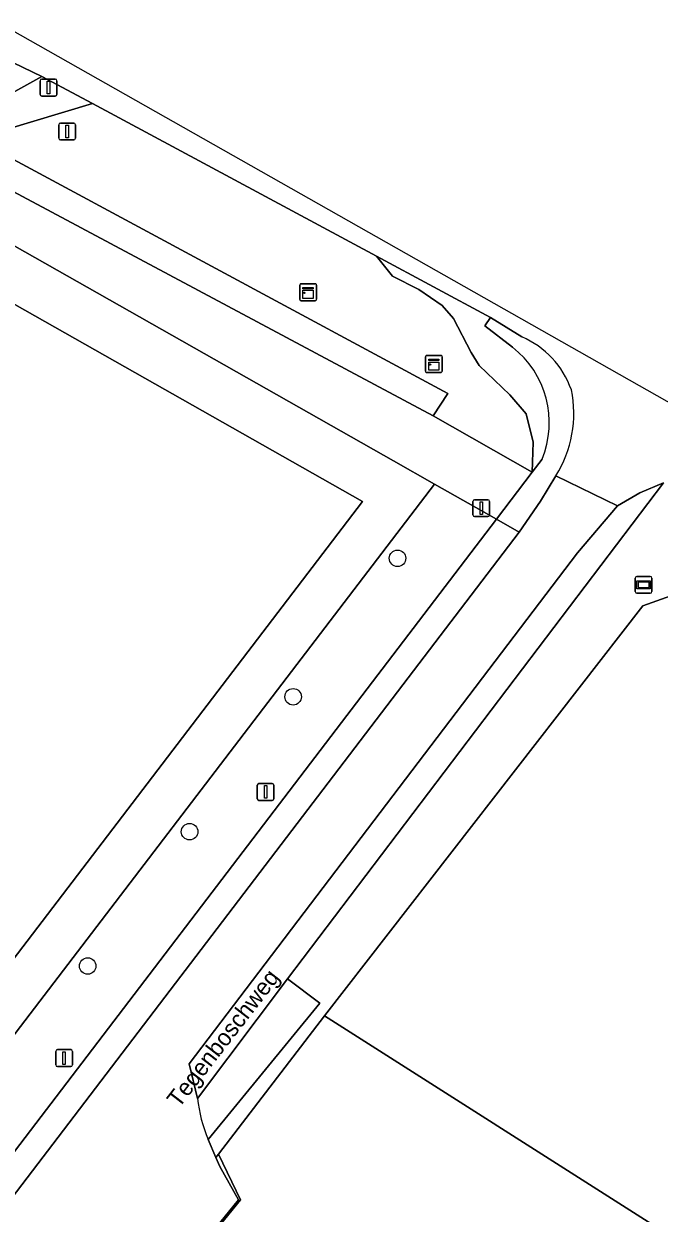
# Model space of a CAD drawing. Extents: x 156502 to 159075, y 384229 to 386100.
# Drawn here: x 157160.6 to 157198.2, y 386014.1 to 386084.5 of the extents above; entities that cross this region are included whole.
import ezdxf

# ---------------------------------------------------------------- set-up
doc = ezdxf.new("R2010")
doc.units = 0
for name, color, linetype in [('IMGEO_Berm_groen', 7, 'Continuous'), ('IMGEO_Berm_halfverhard', 7, 'Continuous'), ('IMGEO_Boom', 7, 'Continuous'), ('IMGEO_Erf', 7, 'Continuous'), ('IMGEO_Fietspad_gesloten', 7, 'Continuous'), ('IMGEO_Gemengd_bos', 7, 'Continuous'), ('IMGEO_Greppel_droge_sloot', 7, 'Continuous'), ('IMGEO_Groenvoorziening', 7, 'Continuous'), ('IMGEO_Haag', 7, 'Continuous'), ('IMGEO_Hek', 7, 'Continuous'), ('IMGEO_Kast', 7, 'Continuous'), ('IMGEO_Lichtmast', 7, 'Continuous'), ('IMGEO_Openbare_ruimte_label', 7, 'Continuous'), ('IMGEO_Rijbaan_lokaal_gesloten', 7, 'Continuous'), ('IMGEO_Rijbaan_lokaal_halfverhard', 7, 'Continuous'), ('IMGEO_Verkeersbordpaal', 7, 'Continuous'), ('IMGEO_Verklikker', 7, 'Continuous')]:
    doc.layers.add(name, color=color, linetype=linetype)

msp = doc.modelspace()

# ---------------------------------------------------------------- linework, layer by layer
at = {"layer": 'IMGEO_Berm_groen'}
msp.add_lwpolyline([(157164.639, 386079.76), (157157.67, 386077.678), (157185.693, 386062.601), (157184.83, 386061.273), (157190.693, 386057.95), (157190.736, 386059.722), (157190.328, 386061.393), (157189.36, 386062.527), (157187.537, 386064.254), (157187.068, 386065.019), (157186.032, 386067.042), (157185.351, 386067.805), (157183.979, 386068.757), (157182.415, 386069.546), (157181.467, 386070.721)], close=True, dxfattribs=at)
for points in [[(157188.566, 386055.162), (157184.907, 386057.234), (157021.918, 385843.894)], [(157027.777, 385843.918), (157039.623, 385859.739), (157076.319, 385908.026), (157188.566, 386055.162)]]:
    msp.add_lwpolyline(points, dxfattribs=at)
at = {"layer": 'IMGEO_Berm_halfverhard'}
msp.add_lwpolyline([(157028.972, 385842.844), (157041.694, 385859.803), (157077.656, 385907.175), (157189.916, 386054.397), (157188.566, 386055.162), (157076.319, 385908.026), (157039.623, 385859.739), (157027.777, 385843.918), (157027.693, 385843.804)], dxfattribs=at)
at = {"layer": 'IMGEO_Boom'}
for centre in [(157182.711, 386052.847), (157176.529, 386044.651), (157170.396, 386036.664), (157164.36, 386028.715)]:
    msp.add_circle(centre, 0.489, dxfattribs=at)
at = {"layer": 'IMGEO_Erf'}
msp.add_lwpolyline([(157291.797, 385905.791), (157257.608, 385922.624), (157240.005, 385933.444), (157265.451, 385970.38), (157218.887, 386000), (157178.386, 386025.763), (157172.105, 386017.583), (157173.41, 386014.873), (157171.433, 386012.444), (157168.449, 386012.84), (157142.059, 385978.178), (157143.255, 385977.636), (157149.373, 385974.096), (157147.133, 385970.598), (157142.453, 385973.429), (157107.2, 385927.397), (157118.024, 385920.915), (157113.026, 385912.196)], dxfattribs=at)
at = {"layer": 'IMGEO_Fietspad_gesloten'}
msp.add_lwpolyline([(157073.59, 386031.17), (157090.661, 386041.292), (157160.05, 386080.464), (157161.641, 386081.37), (157157.693, 386083.251), (157155.519, 386082.013), (157088.994, 386044.123), (157072.063, 386034.271)], dxfattribs=at)
at = {"layer": 'IMGEO_Gemengd_bos'}
msp.add_lwpolyline([(157202.772, 386052.013), (157197.243, 386050.03), (157178.386, 386025.763), (157218.887, 386000), (157265.451, 385970.38), (157240.005, 385933.444), (157257.608, 385922.624), (157291.797, 385905.791), (157297.291, 385911.485), (157341.884, 385885.733), (157336.953, 385876.45), (157374.534, 385855.112), (157371.55, 385848.547), (157374.235, 385846.993), (157374.53, 385846.953), (157374.766, 385847.134), (157419.092, 385923.885)], dxfattribs=at)
at = {"layer": 'IMGEO_Greppel_droge_sloot'}
msp.add_lwpolyline([(157157.67, 386077.678), (157157.203, 386076.568), (157157.01, 386076.109), (157184.83, 386061.273), (157185.693, 386062.601)], close=True, dxfattribs=at)
at = {"layer": 'IMGEO_Groenvoorziening'}
for points in [[(157061.311, 386021.393), (157085.574, 386036.103), (157115.223, 386052.978), (157120.284, 386055.801), (157152.797, 386073.936), (157157.01, 386076.109), (157157.203, 386076.568), (157157.67, 386077.678), (157164.639, 386079.76), (157161.641, 386081.37), (157160.05, 386080.464), (157090.661, 386041.292), (157073.59, 386031.17)], [(157021.918, 385843.894), (157184.907, 386057.234), (157182.471, 386058.613), (157155.614, 386073.823), (157152.797, 386073.936)], [(156974.125, 385919.066), (156965.937, 385930.622), (156962.206, 385939.803), (156996.417, 385971.473), (157033.353, 385999.519), (157071.795, 386022.274), (157107.644, 386042.332), (157141.859, 386060.718), (157157.667, 386069.213), (157180.634, 386056.206), (157071.087, 385912.699)], [(157198.463, 386057.309), (157176.201, 386027.966), (157178.116, 386026.513), (157171.498, 386018.457), (157171.955, 386017.388), (157172.105, 386017.583), (157178.386, 386025.763), (157197.243, 386050.03), (157202.772, 386052.013)], [(157171.498, 386018.457), (157178.116, 386026.513), (157176.201, 386027.966), (157170.869, 386020.883)]]:
    msp.add_lwpolyline(points, dxfattribs=at)
for points in [[(157190.693, 386057.95), (157184.83, 386061.273), (157157.01, 386076.109), (157152.797, 386073.936), (157155.614, 386073.823), (157182.471, 386058.613), (157184.907, 386057.234), (157188.566, 386055.162)], [(157180.634, 386056.206), (157157.667, 386069.213), (157141.859, 386060.718), (157119.898, 386031.613), (157112.225, 386027.38), (157100.054, 386012.563), (157083.49, 386002.815), (157074.431, 385999.041), (157069.734, 385990.233), (157066.45, 385980.334), (157048.46, 385958.059), (157049.783, 385948.534), (157024.383, 385917.578), (157012.477, 385911.492), (157001.337, 385911.378), (156999.468, 385912.632), (156989.301, 385898.643), (156990.12, 385896.678), (157010.156, 385862.563), (157019.003, 385846.692), (157019.844, 385845.786), (157029.054, 385857.935), (157071.087, 385912.699)], [(157168.449, 386012.84), (157171.433, 386012.444), (157173.41, 386014.873), (157172.105, 386017.583), (157171.955, 386017.388), (157172.189, 386016.84), (157173.283, 386014.882), (157171.41, 386012.563), (157170.093, 386012.849), (157168.575, 386013.006)]]:
    msp.add_lwpolyline(points, close=True, dxfattribs=at)
msp.add_arc((157178.911, 386021.674), 8.081, 185.61452, 203.45603, dxfattribs=at)
at = {"layer": 'IMGEO_Haag'}
msp.add_lwpolyline([(157171.498, 386018.457), (157178.116, 386026.513), (157176.201, 386027.966), (157170.869, 386020.883)], dxfattribs=at)
msp.add_arc((157178.911, 386021.674), 8.081, 185.61452, 203.45603, dxfattribs=at)
at = {"layer": 'IMGEO_Hek'}
for points in [[(157182.471, 386058.613), (157155.614, 386073.823), (157152.797, 386073.936)], [(157184.907, 386057.234), (157182.471, 386058.613)], [(157188.566, 386055.162), (157184.907, 386057.234)], [(157189.916, 386054.397), (157188.566, 386055.162)], [(157173.41, 386014.873), (157172.105, 386017.583), (157178.386, 386025.763)], [(157178.386, 386025.763), (157218.887, 386000), (157265.451, 385970.38), (157240.005, 385933.444)], [(157171.433, 386012.444), (157173.41, 386014.873)]]:
    msp.add_lwpolyline(points, dxfattribs=at)
at = {"layer": 'IMGEO_Kast'}
for p, q in [((157176.916, 386068.166), (157176.916, 386069.007)), ((157176.916, 386069.007), (157176.916, 386068.166)), ((157176.991, 386069.091), (157177.832, 386069.091)), ((157177.832, 386069.091), (157176.991, 386069.091)), ((157177.916, 386069.016), (157177.916, 386068.175)), ((157177.916, 386068.175), (157177.916, 386069.016)), ((157177.841, 386068.091), (157177, 386068.091)), ((157177, 386068.091), (157177.841, 386068.091)), ((157184.361, 386063.922), (157184.361, 386064.763)), ((157184.361, 386064.763), (157184.361, 386063.922)), ((157184.436, 386064.847), (157185.277, 386064.847)), ((157185.277, 386064.847), (157184.436, 386064.847)), ((157185.361, 386064.772), (157185.361, 386063.931)), ((157185.361, 386063.931), (157185.361, 386064.772)), ((157185.286, 386063.847), (157184.445, 386063.847)), ((157184.445, 386063.847), (157185.286, 386063.847))]:
    msp.add_line(p, q, dxfattribs=at)
for points in [[(157177.111, 386068.881), (157177.711, 386068.881), (157177.711, 386068.796), (157177.111, 386068.796), (157177.111, 386068.881)], [(157177.111, 386068.706), (157177.711, 386068.706), (157177.711, 386068.217), (157177.111, 386068.217), (157177.111, 386068.706)], [(157184.556, 386064.637), (157185.156, 386064.637), (157185.156, 386064.552), (157184.556, 386064.552), (157184.556, 386064.637)], [(157184.556, 386064.462), (157185.156, 386064.462), (157185.156, 386063.973), (157184.556, 386063.973), (157184.556, 386064.462)]]:
    msp.add_lwpolyline(points, dxfattribs=at)
for centre in [(157177.195, 386068.555), (157184.64, 386064.311)]:
    msp.add_circle(centre, 0.0377, dxfattribs=at)
for centre, start, end in [((157176.994, 386069.013), 92.4484, 184.28452), ((157176.994, 386069.013), 92.4484, 184.28452), ((157177.838, 386069.013), 2.4484, 94.28452), ((157177.838, 386069.013), 2.4484, 94.28452), ((157177.838, 386068.169), 272.4484, 4.28452), ((157177.838, 386068.169), 272.4484, 4.28452), ((157176.994, 386068.169), 182.4484, 274.28452), ((157176.994, 386068.169), 182.4484, 274.28452), ((157184.439, 386064.769), 92.4484, 184.28452), ((157184.439, 386064.769), 92.4484, 184.28452), ((157185.283, 386064.769), 2.4484, 94.28452), ((157185.283, 386064.769), 2.4484, 94.28452), ((157184.439, 386063.925), 182.4484, 274.28452), ((157184.439, 386063.925), 182.4484, 274.28452), ((157185.283, 386063.925), 272.4484, 4.28452), ((157185.283, 386063.925), 272.4484, 4.28452)]:
    msp.add_arc(centre, 0.0779, start, end, dxfattribs=at)
at = {"layer": 'IMGEO_Lichtmast'}
for p, q in [((157187.177, 386055.412), (157187.177, 386056.212)), ((157187.177, 386056.212), (157187.177, 386055.412)), ((157187.277, 386056.312), (157188.067, 386056.312)), ((157188.067, 386056.312), (157187.277, 386056.312)), ((157188.167, 386056.212), (157188.167, 386055.412)), ((157188.167, 386055.412), (157188.167, 386056.212)), ((157188.067, 386055.312), (157187.277, 386055.312)), ((157187.277, 386055.312), (157188.067, 386055.312)), ((157174.405, 386038.617), (157174.405, 386039.417)), ((157174.405, 386039.417), (157174.405, 386038.617)), ((157174.505, 386039.517), (157175.295, 386039.517)), ((157175.295, 386039.517), (157174.505, 386039.517)), ((157175.395, 386039.417), (157175.395, 386038.617)), ((157175.395, 386038.617), (157175.395, 386039.417)), ((157175.295, 386038.517), (157174.505, 386038.517)), ((157174.505, 386038.517), (157175.295, 386038.517)), ((157162.465, 386022.865), (157162.465, 386023.665)), ((157162.465, 386023.665), (157162.465, 386022.865)), ((157162.565, 386023.765), (157163.355, 386023.765)), ((157163.355, 386023.765), (157162.565, 386023.765)), ((157163.455, 386023.665), (157163.455, 386022.865)), ((157163.455, 386022.865), (157163.455, 386023.665)), ((157163.355, 386022.765), (157162.565, 386022.765)), ((157162.565, 386022.765), (157163.355, 386022.765))]:
    msp.add_line(p, q, dxfattribs=at)
for points in [[(157187.597, 386056.187), (157187.747, 386056.187), (157187.747, 386055.437), (157187.597, 386055.437), (157187.597, 386056.187)], [(157174.825, 386039.392), (157174.975, 386039.392), (157174.975, 386038.642), (157174.825, 386038.642), (157174.825, 386039.392)], [(157162.885, 386023.64), (157163.035, 386023.64), (157163.035, 386022.89), (157162.885, 386022.89), (157162.885, 386023.64)]]:
    msp.add_lwpolyline(points, dxfattribs=at)
for centre, start, end in [((157187.277, 386056.212), 90, 180), ((157187.277, 386056.212), 90, 180), ((157188.067, 386056.212), 0, 90), ((157188.067, 386056.212), 360, 90), ((157187.277, 386055.412), 180, 270), ((157187.277, 386055.412), 180, 270), ((157188.067, 386055.412), 270, 0), ((157188.067, 386055.412), 270, 0), ((157174.505, 386039.417), 90, 180), ((157174.505, 386039.417), 90, 180), ((157175.295, 386039.417), 0, 90), ((157175.295, 386039.417), 360, 90), ((157174.505, 386038.617), 180, 270), ((157174.505, 386038.617), 180, 270), ((157175.295, 386038.617), 270, 0), ((157175.295, 386038.617), 270, 0), ((157162.565, 386023.665), 90, 180), ((157162.565, 386023.665), 90, 180), ((157163.355, 386023.665), 0, 90), ((157163.355, 386023.665), 360, 90), ((157162.565, 386022.865), 180, 270), ((157162.565, 386022.865), 180, 270), ((157163.355, 386022.865), 270, 0), ((157163.355, 386022.865), 270, 0)]:
    msp.add_arc(centre, 0.1, start, end, dxfattribs=at)
at = {"layer": 'IMGEO_Rijbaan_lokaal_gesloten'}
for points in [[(157207.296, 386057.251), (157159.198, 386084.481), (157157.693, 386083.251), (157161.641, 386081.37), (157164.639, 386079.76), (157181.467, 386070.721), (157188.215, 386067.097), (157190.071, 386065.952)], [(157170.869, 386020.883), (157170.373, 386022.922), (157193.363, 386053.168), (157195.745, 386055.945), (157192.084, 386057.732), (157191.18, 386056.232), (157189.916, 386054.397), (157077.656, 385907.175), (157041.694, 385859.803), (157028.972, 385842.844), (157031.66, 385840.505)], [(157192.084, 386057.732), (157195.745, 386055.945), (157197.059, 386056.715), (157198.463, 386057.309)], [(157090.505, 385918.168), (157162.952, 386013.182), (157164.84, 386013.11), (157168.146, 386013.05), (157168.575, 386013.006), (157170.093, 386012.849), (157171.41, 386012.563), (157173.283, 386014.882), (157172.189, 386016.84), (157171.955, 386017.388), (157171.498, 386018.457)]]:
    msp.add_lwpolyline(points, dxfattribs=at)
for centre, radius, start, end in [((157187.955, 386061.029), 5.359, 19.5405, 66.73871), ((157186.265, 386061.413), 6.886, 327.68416, 11.79929), ((157178.911, 386021.674), 8.081, 185.61452, 203.45603)]:
    msp.add_arc(centre, radius, start, end, dxfattribs=at)
at = {"layer": 'IMGEO_Rijbaan_lokaal_halfverhard'}
for points in [[(157189.519, 386065.342), (157187.873, 386066.607), (157188.215, 386067.097), (157181.467, 386070.721), (157182.415, 386069.546), (157183.979, 386068.757), (157185.351, 386067.805), (157186.032, 386067.042), (157187.068, 386065.019), (157187.537, 386064.254), (157189.36, 386062.527), (157190.328, 386061.393), (157190.736, 386059.722), (157190.693, 386057.95), (157191.268, 386058.707)], [(157190.071, 386065.952), (157188.215, 386067.097), (157187.873, 386066.607), (157189.519, 386065.342)], [(157191.268, 386058.707), (157190.693, 386057.95), (157188.566, 386055.162), (157189.916, 386054.397), (157191.18, 386056.232), (157192.084, 386057.732)]]:
    msp.add_lwpolyline(points, dxfattribs=at)
msp.add_lwpolyline([(157198.463, 386057.309), (157197.059, 386056.715), (157195.745, 386055.945), (157193.363, 386053.168), (157170.373, 386022.922), (157170.869, 386020.883), (157176.201, 386027.966)], close=True, dxfattribs=at)
for centre, radius, start, end in [((157187.955, 386061.029), 5.359, 19.5405, 66.73871), ((157186.023, 386060.872), 5.674, 337.56475, 51.96998), ((157186.023, 386060.872), 5.674, 337.56475, 51.96998), ((157186.265, 386061.413), 6.886, 327.68416, 11.79929)]:
    msp.add_arc(centre, radius, start, end, dxfattribs=at)
at = {"layer": 'IMGEO_Verkeersbordpaal'}
for p, q in [((157161.545, 386080.306), (157161.545, 386081.106)), ((157161.545, 386081.106), (157161.545, 386080.306)), ((157161.645, 386081.206), (157162.435, 386081.206)), ((157162.435, 386081.206), (157161.645, 386081.206)), ((157162.535, 386081.106), (157162.535, 386080.306)), ((157162.535, 386080.306), (157162.535, 386081.106)), ((157162.435, 386080.206), (157161.645, 386080.206)), ((157161.645, 386080.206), (157162.435, 386080.206)), ((157162.647, 386077.704), (157162.647, 386078.504)), ((157162.647, 386078.504), (157162.647, 386077.704)), ((157162.747, 386078.604), (157163.537, 386078.604)), ((157163.537, 386078.604), (157162.747, 386078.604)), ((157163.637, 386078.504), (157163.637, 386077.704)), ((157163.637, 386077.704), (157163.637, 386078.504)), ((157163.537, 386077.604), (157162.747, 386077.604)), ((157162.747, 386077.604), (157163.537, 386077.604))]:
    msp.add_line(p, q, dxfattribs=at)
for points in [[(157161.965, 386081.081), (157162.115, 386081.081), (157162.115, 386080.331), (157161.965, 386080.331), (157161.965, 386081.081)], [(157163.067, 386078.479), (157163.217, 386078.479), (157163.217, 386077.729), (157163.067, 386077.729), (157163.067, 386078.479)]]:
    msp.add_lwpolyline(points, dxfattribs=at)
for centre, start, end in [((157161.645, 386081.106), 90, 180), ((157161.645, 386081.106), 90, 180), ((157162.435, 386081.106), 0, 90), ((157162.435, 386081.106), 360, 90), ((157161.645, 386080.306), 180, 270), ((157161.645, 386080.306), 180, 270), ((157162.435, 386080.306), 270, 0), ((157162.435, 386080.306), 270, 0), ((157162.747, 386078.504), 90, 180), ((157162.747, 386078.504), 90, 180), ((157163.537, 386078.504), 0, 90), ((157163.537, 386078.504), 360, 90), ((157162.747, 386077.704), 180, 270), ((157162.747, 386077.704), 180, 270), ((157163.537, 386077.704), 270, 0), ((157163.537, 386077.704), 270, 0)]:
    msp.add_arc(centre, 0.1, start, end, dxfattribs=at)
at = {"layer": 'IMGEO_Verklikker'}
for p, q in [((157196.788, 386050.876), (157196.788, 386051.676)), ((157196.788, 386051.676), (157196.788, 386050.876)), ((157196.888, 386051.776), (157197.678, 386051.776)), ((157197.678, 386051.776), (157196.888, 386051.776)), ((157197.778, 386051.676), (157197.778, 386050.876)), ((157197.778, 386050.876), (157197.778, 386051.676)), ((157197.678, 386050.776), (157196.888, 386050.776)), ((157196.888, 386050.776), (157197.678, 386050.776))]:
    msp.add_line(p, q, dxfattribs=at)
for points in [[(157196.889, 386051.508), (157197.677, 386051.508), (157197.677, 386051.044), (157196.889, 386051.044), (157196.889, 386051.508)], [(157196.954, 386051.443), (157196.954, 386051.109), (157197.612, 386051.109), (157197.612, 386051.443), (157196.954, 386051.443)]]:
    msp.add_lwpolyline(points, dxfattribs=at)
for centre, start, end in [((157196.888, 386051.676), 90, 180), ((157196.888, 386051.676), 90, 180), ((157197.678, 386051.676), 0, 90), ((157197.678, 386051.676), 360, 90), ((157196.888, 386050.876), 180, 270), ((157196.888, 386050.876), 180, 270), ((157197.678, 386050.876), 270, 0), ((157197.678, 386050.876), 270, 0)]:
    msp.add_arc(centre, 0.1, start, end, dxfattribs=at)

# ---------------------------------------------------------------- texts
at = {"layer": 'IMGEO_Openbare_ruimte_label'}
msp.add_text('Tegenboschweg', height=1, rotation=52.27073, dxfattribs=at).set_placement((157169.767, 386020.263))

doc.saveas('drawing.dxf')
